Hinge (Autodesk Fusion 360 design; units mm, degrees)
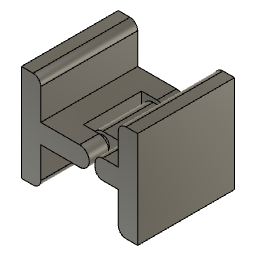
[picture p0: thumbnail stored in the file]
parameter "diameter" = 2.4
parameter "tolerance" = 0.5
sketch "Sketch2" plane through (0, 0, 0) normal (0, 1, 0) x axis (1, 0, 0)
  line L1 (-10, 0) -> (0, 0)
  line L2 (0, -5) -> (-10, -5)
  line L3 (-10, -15) -> (-15, -15)
  line L4 (-15, 10) -> (-10, 10)
  line L5 (-15, -15) -> (-15, 10)
  line L6 (-10, -5) -> (-10, -15)
  line L7 (-10, 10) -> (-10, 0)
  line L8 (-4, 0) -> (-4, -5)
  arc A1 centre (0, -2.5) radius 2.5 clockwise from (0, 0) to (0, -5)
  circle C1 centre (0, -2.5) radius 1.7
  circle C2 centre (0, -2.5) radius 1.2
  point P1 (0, 0)
  point P2 (0, 0)
  point P13 (-4, -5)
  point P14 (-4, 0)
  point P4 (-10, -5)
  point P5 (0, -5)
  point P9 (-15, -15)
  point P12 (-15, 10)
  horizontal L1
  horizontal L2
  coincident P1 P2
  concentric A1 C1
  concentric C1 C2
  horizontal L3
  vertical L6
  horizontal L4
  vertical L5
  collinear L6 L7
  coincident L2 P13
  coincident L1 P14
  perpendicular L1 L8
  dimension "d7" diameter C2 = 2.4 (= "diameter")
  dimension "d8" distance P4 P5 = 10
  dimension "d11" diameter C1 = 3.4 (= "diameter + tolerance * 2")
  dimension "d12" distance P9 P12 = 25
extrude "Extrude1" new body sketch "Sketch2" profile of L1 L2 L3 L7 L4 L5 L8 along normal blind 7
extrude "Extrude2" add sketch "Sketch2" profile of L1 L2 A1 C1 L8 along normal blind 3
component_from_bodies "Body->Comp"
extrude "Extrude1" new body blind 12.5
extrude "Extrude2" add sketch "Sketch2" profile of L1 L2 L3 L7 L4 L5 L8 along normal blind 12.5
extrude "Extrude3" add sketch "Sketch2" profile of L1 L2 A1 C1 L8 along normal blind 5
extrude "Extrude4" add sketch "Sketch2" profile of C1 C2 along normal blind 5
work_plane "WorkPlane1" AlongDistance 0
mirror "Mirror1"
combine "Combine1"
delete_face "DeleteFace1"
fillet "Fillet1" radius 2
sketch "Sketch2" plane through (0, 0, 0) normal (0, 1, 0) x axis (1, 0, 0)
  line L1 (20, 0) -> (10, 0)
  line L2 (10, -5) -> (20, -5)
  line L3 (10, 0) -> (10, -5)
  line L4 (25, -15) -> (20, -15)
  line L5 (25, 10) -> (25, -15)
  line L6 (20, 10) -> (25, 10)
  line L7 (14, 0) -> (14, -5)
  line L8 (20, 0) -> (20, 10)
  line L9 (20, -15) -> (20, -5)
  circle C1 centre (10, -2.5) radius 1.7
  arc A1 centre (10, -2.5) radius 2.5 clockwise from (10, -5) to (10, 0)
  point P6 (10, -2.5)
  point P12 (14, -5)
  point P13 (14, 0)
  point P2 (10, 0)
  point P3 (20, 0)
  point P8 (20, -15)
  point P11 (20, 10)
  horizontal L1
  horizontal L2
  vertical L3
  midpoint L3 P6
  concentric C1 A1
  horizontal L4
  vertical L5
  horizontal L6
  vertical L8
  coincident L2 P12
  coincident L1 P13
  perpendicular L1 L7
  collinear L8 L9
  dimension "d30" distance P2 P3 = 10
  dimension "d31" diameter A1 = 5
  dimension "d33" diameter C1 = 3.4 (= "diameter + tolerance * 2")
  dimension "d34" distance P8 P11 = 25
extrude "Extrude1" new body sketch "Sketch2" profile of L1 L2 L3 C1 L7 along normal blind 14 (= "15 mm - tolerance * 2")
extrude "Extrude2" add sketch "Sketch2" profile of L3 A1 C1 along normal blind 14 (= "15 mm - tolerance * 2")
extrude "Extrude3" add sketch "Sketch2" profile of L1 L2 L4 L5 L6 L9 L7 along normal blind 14 (= "15 mm - tolerance * 2")
extrude "Extrude4" new body sketch "Sketch2" profile of L1 L2 L3 C1 L7 along normal blind 7 (= "( 15 mm - tolerance * 2 ) / 2")
extrude "Extrude5" add sketch "Sketch2" profile of L1 L2 L4 L5 L6 L9 L7 along normal blind 7 (= "( 15 mm - tolerance * 2 ) / 2")
extrude "Extrude6" add sketch "Sketch2" profile of L3 A1 C1 along normal blind 7 (= "( 15 mm - tolerance * 2 ) / 2")
combine "Combine1"
extrude "Extrude7" add sketch "Sketch2" profile of L1 L2 L4 L5 L6 L9 L7 against normal blind 5
mirror "Mirror1"
combine "Combine2"
move "Move1"
extrude "Extrude8" add sketch "Sketch2" profile of L1 L2 L4 L5 L6 L9 L7 along normal blind 25
fillet "Fillet1" radius 2
work_plane "WorkPlane2"
ground "Ground1"
fillet "Fillet2" radius 2
fillet "Fillet3" radius 2
fillet "Fillet4" radius 2
joint "Assemble3" alignAngle 0 alignOffsetX 0 alignOffsetY 0 alignOffsetZ 0 AngleMinimum -55 AngleMaximum 45
extrude "Extrude9" cut of existing geometry no distance stored
extrude "Extrude10" cut of existing geometry no distance stored
extrude "Extrude3" new body sketch "Sketch2" profile of C2 along normal blind 8
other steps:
base_feature "Base Feature"
create_component "CreateComponent1"
remove_body "RemoveBody1"
create_component "CreateComponent3"
joint_origin "JointOrigin3" OffsetX 0 OffsetY 0 OffsetZ 0 AngleZ 0
joint_origin "JointOrigin3" OffsetX 0 OffsetY 0 OffsetZ 0 AngleZ 0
